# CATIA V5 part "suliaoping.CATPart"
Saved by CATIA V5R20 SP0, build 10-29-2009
Part number: 熟料瓶
Bounding box of the stored display mesh (mm): x -25 to 25, y -25 to 27, z 0 to 110
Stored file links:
  E:\3d\suliaoping.CATPart
  E:\CATIA\win_b64\startup\materials\Catalog.CATMaterial
  E:\CATIA\win_b64\startup\materials\pebble.jpg
  E:\CATIA\win_b64\startup\materials\DS_star.jpg
  E:\CATIA\win_b64\startup\materials\birch.jpg
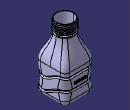
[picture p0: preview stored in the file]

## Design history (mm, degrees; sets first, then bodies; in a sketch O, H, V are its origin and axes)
Body1 (main body), material "无"
  Sketch1 on xy-plane, origin (0, 0, 0), H (1, 0, 0), V (0, 1, 0)
    line L1 (25, 25) -> (25, -25)
    line L2 (25, -25) -> (-25, -25)
    line L3 (-25, -25) -> (-25, 25)
    line L4 (-25, 25) -> (25, 25)
    length L1 = 50
    length L4 = 50
    vertical: L1 V, L3 V
    horizontal: L2 H, L4 H
    equidistance: L1 L3 O, L2 L4 O
  Pad1: profile Sketch1, direction (0, 0, 1), length 50
  Fillet1: on edge [face of Pad1 from Sketch1.L1 | face of Pad1 from Sketch1.L2]; edge [face of Pad1 from Sketch1.L4 | face of Pad1 from Sketch1.L1]; edge [face of Pad1 from Sketch1.L3 | face of Pad1 from Sketch1.L4]; edge [face of Pad1 from Sketch1.L2 | face of Pad1 from Sketch1.L3]
  Fillet2: on edge [start face of Pad1 | face of Pad1 from Sketch1.L2]
  Plane1: type Offset, RefPlane end face of Pad1, Offset 40, reversed
  Sketch2 on Plane1, origin (0, 0, 90), H (1, 0, 0), V (0, -1, 0)
    circle A1 centre (0, 0) radius 15
    radius A1 = 15
  Pad2: profile Sketch2, direction (0, 0, 1), length 20
  Sketch3 on Plane1, origin (0, 0, 90), H (1, 0, 0), V (0, -1, 0)
    point P1 (15, 0)
    distance P1 V = 15
    coincidence: P1 H
  Sketch4 on end face of Pad1, origin (0, 0, 50), H (1, 0, 0), V (0, 1, 0)
    point P1 (25, 0)
    distance P1 V = 25
  Loft1: solid, Sections ({boundary Boundary {extract ExtractElem start face of Pad2}}; {boundary Boundary {extract ExtractElem end face of Pad1}}), StartFace start face of Pad2, EndFace end face of Pad1
  Sketch5 on face of Pad1 from Sketch1.L3, origin (-25, 0, 0), H (0, -1, 0), V (0, 0, 1)
    spline S1 through (-40, 10) (-10, 20) (10, 10) (30, 20)
    spline S2 through (-40, 30) (-10, 40) (10, 30) (30, 40)
  Extrude1: Element1 Sketch5, Lim1 60, Lim2 60
  MultiSel1: CommonCtxFeats ({extract ExtractElem face of Fillet1}; {extract ExtractElem face of Pad1 from Sketch1.L1}; {extract ExtractElem face of Fillet1}; {extract ExtractElem face of Pad1 from Sketch1.L4}; {extract ExtractElem face of Fillet1}; {extract ExtractElem face of Pad1 from Sketch1.L3}; {extract ExtractElem face of Fillet1}; {extract ExtractElem face of Pad1 from Sketch1.L2})
  DatumCurve1 to DatumCurve8
  Line1: stored without definition
  Line2: stored without definition
  DatumCurve9 to DatumCurve11
  Line3: stored without definition
  Line4: stored without definition
  DatumCurve12
  DatumCurve13
  Join1: Elements (Line3; DatumCurve12; DatumCurve7; DatumCurve5; Line1; DatumCurve10; DatumCurve1; DatumCurve3)
  Join2: Elements (DatumCurve13; DatumCurve9; DatumCurve6; Line4; Line2; DatumCurve11; DatumCurve2; DatumCurve4)
  Plane2: type Normal, Curve Join2, RefPoint vertex of MultiSel1
  Plane3: type Normal, Curve Join1, RefPoint vertex of MultiSel1
  Circle1: type CtrRad, Start 0, End 180, Center vertex of MultiSel1, Support Plane2, Radius 2, FirstDirection (1, 0, 0)
  Circle2: type CtrRad, Start 0, End 180, Center vertex of MultiSel1, Support Plane3, Radius 2, FirstDirection (0, -1, 0)
  Slot1: profile Circle1, centre curve Join2
  Slot2: profile Circle2, centre curve Join1
  Shell1: IntOffset 1, Face end face of Pad2, ExtOffset 0
  Point1: (0, 0, 2), relative to Sketch3
  Helix1: Direction Z axis, RefPoint Point1, Pitch 3, Height 16, TaperAngle 0
  Point2: type OnCurve, Support Helix1, RefPoint vertex of Helix1, Length 5
  Point3: type OnCurve, Support Helix1, RefPoint Point1, Length 5
  Point4: (-5, 0, 0), relative to Point1
  Point5: (0, -5, 0), relative to vertex of Helix1
  Line5: type PtPt, FirstPoint vertex of Helix1, SecondPoint Point5
  Line6: type PtPt, FirstPoint Point1, SecondPoint Point4
  Connect1: Curve1 Line6, Point1 Point4, Tension1 1, Curve2 Helix1, Point2 Point3, Tension2 1
  Point6: stored without definition
  Point7: stored without definition
  Connect2: Curve1 Line5, Point1 Point5, Tension1 1, Curve2 Connect1, Point2 Point7, Tension2 1
  Plane4: type Normal, Curve Connect2, RefPoint Point4
  Circle3: type CtrRad, Start 0, End 180, Center Point4, Support Plane4, Radius 1, FirstDirection (0, 1, 0)
  Rib1: profile Circle3, centre curve Connect2
  Body2
    Sketch6 on Plane1, origin (0, 0, 90), H (1, 0, 0), V (0, -1, 0)
      circle A1 centre (0, 0) radius 14
      polyline C1
      polyline C2
      polyline C3
      polyline C4
      polyline C5
      polyline C6
      polyline C7
      polyline C8
      polyline C9
      polyline C10
      polyline C11
      radius A1 = 14
    Pad3: profile Sketch6, direction (0, 0, 1), length 20
  Remove1: tool Body2
  Sketch7 on face of Pad1 from Sketch1.L4, origin (0, 25, 0), H (-1, 0, 0), V (0, 0, 1)
    polyline C1
    polyline C2
    polyline C3
    polyline C4
    polyline C5
    polyline C6
    polyline C7
    polyline C8
    polyline C9
    polyline C10
    polyline C11
  Pad4: profile Sketch7, direction (0, 1, 0), length 2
